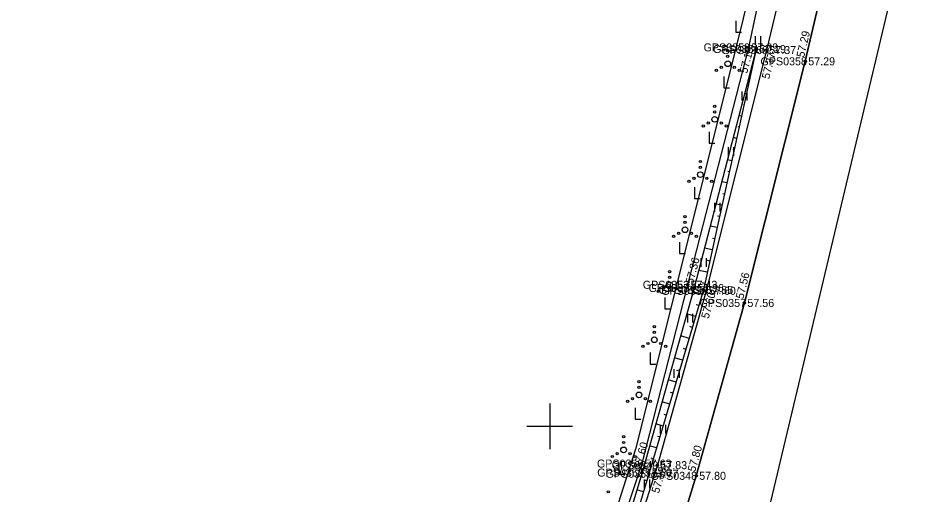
# Model space of a CAD drawing. Extents: x 551623 to 559850, y 6561220 to 6567135.
# Drawn here: x 556603.5 to 556683.3, y 6562994 to 6563035.7 of the extents above; entities that cross this region are included whole.
import ezdxf

# ---------------------------------------------------------------- set-up
doc = ezdxf.new("R2010")
doc.units = 0
for name, color, linetype in [('HALJASTUS', 7, 'Continuous'), ('KORGUS-EH2000', 7, 'Continuous'), ('MOOTKORG-EH2000', 7, 'Continuous'), ('MOOTMPUNKT', 7, 'Continuous'), ('MOOTNR', 7, 'Continuous'), ('MOOTPIIR', 7, 'Continuous'), ('PIIR', 7, 'Continuous'), ('RELJEEF', 7, 'Continuous'), ('TEE', 7, 'Continuous'), ('VORK', 7, 'Continuous')]:
    doc.layers.add(name, color=color, linetype=linetype)

msp = doc.modelspace()

# ---------------------------------------------------------------- linework, layer by layer
at = {"layer": 'HALJASTUS'}
for p, q in [((556666.281, 6563035.489), (556666.281, 6563034.489)), ((556666.281, 6563034.489), (556666.781, 6563034.489)), ((556667.98, 6563034.138), (556667.98, 6563033.377)), ((556668.435, 6563034.138), (556668.435, 6563033.377)), ((556665.226, 6563030.602), (556665.226, 6563029.602)), ((556665.226, 6563029.602), (556665.726, 6563029.602)), ((556666.792, 6563029.281), (556666.792, 6563028.52)), ((556667.247, 6563029.281), (556667.247, 6563028.52)), ((556663.952, 6563025.767), (556663.952, 6563024.767)), ((556663.952, 6563024.767), (556664.452, 6563024.767)), ((556665.605, 6563024.424), (556665.605, 6563023.663)), ((556666.06, 6563024.424), (556666.06, 6563023.663)), ((556662.657, 6563020.938), (556662.657, 6563019.938)), ((556662.657, 6563019.938), (556663.157, 6563019.938)), ((556664.418, 6563019.567), (556664.418, 6563018.806)), ((556664.873, 6563019.567), (556664.873, 6563018.806)), ((556661.363, 6563016.108), (556661.363, 6563015.108)), ((556661.363, 6563015.108), (556661.863, 6563015.108)), ((556663.231, 6563014.71), (556663.231, 6563013.949)), ((556663.686, 6563014.71), (556663.686, 6563013.949)), ((556660.068, 6563011.278), (556660.068, 6563010.278)), ((556660.068, 6563010.278), (556660.568, 6563010.278)), ((556662.044, 6563009.853), (556662.044, 6563009.092)), ((556662.499, 6563009.853), (556662.499, 6563009.092)), ((556658.774, 6563006.449), (556658.774, 6563005.449)), ((556658.774, 6563005.449), (556659.274, 6563005.449)), ((556660.856, 6563004.996), (556660.856, 6563004.235)), ((556661.311, 6563004.996), (556661.311, 6563004.235)), ((556657.479, 6563001.619), (556657.479, 6563000.619)), ((556657.479, 6563000.619), (556657.979, 6563000.619)), ((556659.669, 6563000.139), (556659.669, 6562999.378)), ((556660.124, 6563000.139), (556660.124, 6562999.378)), ((556656.057, 6562996.826), (556656.057, 6562995.826)), ((556656.057, 6562995.826), (556656.557, 6562995.826)), ((556658.263, 6562995.342), (556658.263, 6562994.58)), ((556658.718, 6562995.342), (556658.718, 6562994.58))]:
    msp.add_line(p, q, dxfattribs=at)
msp.add_lwpolyline([(556730.179, 6563321.969), (556724.636, 6563294.498), (556716.875, 6563261.024), (556713.058, 6563244.418), (556708.579, 6563223.732), (556703.725, 6563202.879), (556698.774, 6563180.185), (556694.069, 6563158.747), (556689.217, 6563135.017), (556684.659, 6563113.963), (556681.417, 6563095.607), (556676.704, 6563073.757), (556671.602, 6563053.044), (556667.381, 6563033.155), (556662.058, 6563012.385), (556658.05, 6562996.741), (556653.492, 6562982.863), (556651.045, 6562972.787), (556648.491, 6562966.927), (556641.785, 6562944.892), (556639.351, 6562934.359)], dxfattribs=at)
for centre, radius in [((556665.575, 6563032.875), 0.1), ((556665.575, 6563032.375), 0.1), ((556665.01, 6563031.4), 0.1), ((556665.575, 6563031.725), 0.25), ((556666.14, 6563031.4), 0.1), ((556664.575, 6563031.15), 0.1), ((556666.575, 6563031.15), 0.1), ((556664.435, 6563028.007), 0.1), ((556664.435, 6563027.507), 0.1), ((556663.87, 6563026.532), 0.1), ((556664.435, 6563026.857), 0.25), ((556665, 6563026.532), 0.1), ((556663.435, 6563026.282), 0.1), ((556665.435, 6563026.282), 0.1), ((556663.175, 6563023.169), 0.1), ((556663.175, 6563022.669), 0.1), ((556662.61, 6563021.694), 0.1), ((556663.175, 6563022.019), 0.25), ((556663.74, 6563021.694), 0.1), ((556662.175, 6563021.444), 0.1), ((556664.175, 6563021.444), 0.1), ((556661.833, 6563018.353), 0.1), ((556661.833, 6563017.853), 0.1), ((556661.833, 6563017.203), 0.25), ((556660.833, 6563016.628), 0.1), ((556661.268, 6563016.878), 0.1), ((556662.398, 6563016.878), 0.1), ((556662.833, 6563016.628), 0.1), ((556660.49, 6563013.536), 0.1), ((556660.49, 6563013.036), 0.1), ((556660.49, 6563012.386), 0.25), ((556659.49, 6563011.811), 0.1), ((556659.925, 6563012.061), 0.1), ((556661.055, 6563012.061), 0.1), ((556661.49, 6563011.811), 0.1), ((556659.148, 6563008.72), 0.1), ((556659.148, 6563008.22), 0.1), ((556659.148, 6563007.57), 0.25), ((556658.148, 6563006.995), 0.1), ((556658.583, 6563007.245), 0.1), ((556659.713, 6563007.245), 0.1), ((556660.148, 6563006.995), 0.1), ((556657.806, 6563003.903), 0.1), ((556657.806, 6563003.403), 0.1), ((556657.806, 6563002.753), 0.25), ((556656.806, 6563002.178), 0.1), ((556657.241, 6563002.428), 0.1), ((556658.371, 6563002.428), 0.1), ((556658.806, 6563002.178), 0.1), ((556656.463, 6562999.087), 0.1), ((556656.463, 6562998.587), 0.1), ((556656.463, 6562997.937), 0.25), ((556655.463, 6562997.362), 0.1), ((556655.898, 6562997.612), 0.1), ((556657.028, 6562997.612), 0.1), ((556657.463, 6562997.362), 0.1), ((556655.121, 6562994.27), 0.1)]:
    msp.add_circle(centre, radius, dxfattribs=at)
at = {"layer": 'KORGUS-EH2000'}
for centre in [(556668.063, 6563033.012), (556668.948, 6563032.918), (556672.356, 6563031.934), (556662.638, 6563012.103), (556663.677, 6563011.856), (556667.03, 6563010.794), (556659.413, 6562996.602), (556658.074, 6562995.952), (556662.813, 6562995.67)]:
    msp.add_circle(centre, 0.1, dxfattribs=at)
at = {"layer": 'MOOTMPUNKT'}
for centre in [(556667.381, 6563033.155), (556668.063, 6563033.012), (556668.948, 6563032.918), (556672.356, 6563031.934), (556662.058, 6563012.385), (556662.638, 6563012.103), (556663.448, 6563011.932), (556663.677, 6563011.856), (556667.03, 6563010.794), (556658.05, 6562996.741), (556659.413, 6562996.602), (556658.074, 6562995.952), (556658.666, 6562995.849), (556662.813, 6562995.67)]:
    msp.add_circle(centre, 0.1, dxfattribs=at)
at = {"layer": 'MOOTPIIR'}
for points in [[(556730.032, 6563322.014), (556724.172, 6563296.078), (556712.209, 6563244.927), (556703.118, 6563205.314), (556697.492, 6563180.798), (556687.922, 6563135.477), (556675.757, 6563074.837), (556666.859, 6563035.417), (556657.51, 6562997.998), (556646.614, 6562963.869), (556636.734, 6562934.522), (556635.188, 6562922.976), (556635.168, 6562919.001), (556632.094, 6562895.441), (556631.237, 6562879.275), (556626.788, 6562853.34), (556618.715, 6562822.195), (556606.273, 6562747.18)], [(556615.494, 6562765.342), (556618.725, 6562784.886), (556621.895, 6562802.833), (556624.976, 6562818.135), (556627.451, 6562830.139), (556630.417, 6562842.272), (556632.841, 6562852.218), (556634.314, 6562860.895), (556636.03, 6562872.421), (556636.878, 6562879.2), (556638.458, 6562894.387), (556639.853, 6562906.55), (556642.2, 6562921.204), (556644.444, 6562933.125), (556647.058, 6562944.293), (556652.609, 6562963.065), (556658.348, 6562981.124), (556662.813, 6562995.67), (556667.03, 6563010.794), (556672.356, 6563031.934), (556677.036, 6563051.97)]]:
    msp.add_lwpolyline(points, dxfattribs=at)
at = {"layer": 'PIIR'}
msp.add_lwpolyline([(555805.16, 6562850.3), (555826.95, 6563063.64), (555846.51, 6563164.12), (555894.51, 6563325.36), (556136, 6563572.22), (556237.49, 6563672.14), (556288.75, 6563676.33), (556560.07, 6563698.51), (556620.28, 6563801.97), (556702.51, 6563943.25), (556780.4, 6563955.1), (556879.9, 6563970.48), (556759.6, 6563438.6), (556685.3, 6563096.1), (556692.98, 6563093.02), (556667.97, 6562987.78), (556646.18, 6562894.39), (556231.34, 6562873.47), (556132.45, 6562866.66), (555973.8, 6562858.59)], close=True, dxfattribs=at)
at = {"layer": 'RELJEEF'}
for p, q in [((556667.635, 6563031.058), (556667.561, 6563031.075)), ((556667.422, 6563030.081), (556667.388, 6563030.089)), ((556667.208, 6563029.104), (556667.058, 6563029.137)), ((556666.994, 6563028.128), (556666.938, 6563028.14)), ((556666.78, 6563027.151), (556666.555, 6563027.2)), ((556666.566, 6563026.174), (556666.487, 6563026.191)), ((556666.352, 6563025.197), (556666.053, 6563025.263)), ((556666.138, 6563024.22), (556666.037, 6563024.242)), ((556665.924, 6563023.243), (556665.55, 6563023.325)), ((556665.71, 6563022.266), (556665.587, 6563022.294)), ((556665.496, 6563021.29), (556665.047, 6563021.388)), ((556665.283, 6563020.313), (556665.137, 6563020.345)), ((556665.069, 6563019.336), (556664.545, 6563019.451)), ((556664.855, 6563018.359), (556664.686, 6563018.396)), ((556664.641, 6563017.382), (556664.042, 6563017.513)), ((556664.427, 6563016.405), (556664.236, 6563016.447)), ((556664.213, 6563015.428), (556663.539, 6563015.576)), ((556663.999, 6563014.452), (556663.786, 6563014.498)), ((556663.785, 6563013.475), (556663.037, 6563013.639)), ((556663.571, 6563012.498), (556663.336, 6563012.55)), ((556663.328, 6563011.529), (556662.542, 6563011.762)), ((556663.043, 6563010.57), (556662.811, 6563010.639)), ((556662.758, 6563009.612), (556661.998, 6563009.838)), ((556662.473, 6563008.653), (556662.249, 6563008.72)), ((556662.188, 6563007.695), (556661.454, 6563007.913)), ((556661.903, 6563006.736), (556661.686, 6563006.8)), ((556661.618, 6563005.778), (556660.91, 6563005.988)), ((556661.333, 6563004.819), (556661.124, 6563004.881)), ((556661.048, 6563003.861), (556660.366, 6563004.063)), ((556660.763, 6563002.902), (556660.562, 6563002.962)), ((556660.478, 6563001.943), (556659.822, 6563002.138)), ((556660.193, 6563000.985), (556660, 6563001.042)), ((556659.908, 6563000.026), (556659.279, 6563000.213)), ((556659.623, 6562999.068), (556659.438, 6562999.123)), ((556659.338, 6562998.109), (556658.735, 6562998.289)), ((556659.053, 6562997.151), (556658.876, 6562997.203)), ((556658.768, 6562996.192), (556658.191, 6562996.364)), ((556658.482, 6562995.234), (556658.31, 6562995.285)), ((556658.196, 6562994.276), (556657.622, 6562994.447))]:
    msp.add_line(p, q, dxfattribs=at)
for points in [[(556668.063, 6563033.012), (556662.638, 6563012.103), (556658.074, 6562995.952), (556654.068, 6562982.624), (556648.67, 6562964.128), (556645.882, 6562956.383)], [(556668.063, 6563033.012), (556663.448, 6563011.932), (556658.666, 6562995.849), (556654.666, 6562982.46), (556649.054, 6562963.975), (556645.882, 6562956.383)]]:
    msp.add_lwpolyline(points, dxfattribs=at)
at = {"layer": 'TEE'}
for points in [[(556673.702, 6563052.755), (556668.948, 6563032.918), (556663.677, 6563011.856), (556659.413, 6562996.602), (556654.921, 6562982.331), (556649.346, 6562963.956), (556643.856, 6562944.887), (556641.251, 6562934.032), (556638.558, 6562921.526), (556636.805, 6562918.668), (556636.945, 6562916.523), (556637.3, 6562914.816), (556636.499, 6562907.225), (556635.077, 6562894.963), (556633.622, 6562879.411), (556632.944, 6562873.135), (556630.86, 6562861.302), (556629.252, 6562852.948), (556627.08, 6562842.719), (556624.546, 6562830.858), (556621.61, 6562818.841), (556618.964, 6562803.304), (556615.61, 6562785.44), (556612.253, 6562766.582)], [(556677.036, 6563051.97), (556672.356, 6563031.934), (556667.03, 6563010.794), (556662.813, 6562995.67), (556658.348, 6562981.124), (556652.609, 6562963.065), (556647.058, 6562944.293), (556644.444, 6562933.125), (556642.2, 6562921.204), (556639.853, 6562906.55), (556638.458, 6562894.387), (556636.878, 6562879.2), (556636.03, 6562872.421), (556634.314, 6562860.895), (556632.841, 6562852.218), (556630.417, 6562842.272), (556627.451, 6562830.139), (556624.976, 6562818.135), (556621.895, 6562802.833), (556618.725, 6562784.886), (556615.494, 6562765.342)]]:
    msp.add_lwpolyline(points, dxfattribs=at)
at = {"layer": 'VORK'}
for p, q in [((556650, 6563002), (556650, 6562998)), ((556648, 6563000), (556652, 6563000))]:
    msp.add_line(p, q, dxfattribs=at)

# ---------------------------------------------------------------- texts
at = {"layer": 'KORGUS-EH2000'}
for s, rotation, p in [(' 57.29', 76.85448, (556672.186, 6563031.974)), (' 57.19', 75.45465, (556667.198, 6563030.574)), (' 57.37', 75.95044, (556669.141, 6563030.09)), (' 57.36', 75.45465, (556662.469, 6563012.146)), (' 57.56', 75.85903, (556666.861, 6563010.837)), (' 57.60', 74.38264, (556663.825, 6563009.118)), (' 57.60', 74.2216, (556657.906, 6562996)), (' 57.80', 74.41953, (556662.645, 6562995.717)), (' 57.83', 72.52713, (556659.461, 6562993.836))]:
    msp.add_text(s, height=0.7, rotation=rotation, dxfattribs=at).set_placement(p)
at = {"layer": 'MOOTKORG-EH2000'}
for s, p in [(' 57.09', (556667.381, 6563032.805)), (' 57.19', (556668.063, 6563032.662)), (' 57.37', (556668.948, 6563032.568)), (' 57.29', (556672.356, 6563031.584)), (' 57.43', (556662.058, 6563012.035)), (' 57.36', (556662.638, 6563011.753)), (' 57.55', (556663.448, 6563011.582)), (' 57.60', (556663.677, 6563011.506)), (' 57.56', (556667.03, 6563010.444)), (' 57.63', (556658.05, 6562996.391)), (' 57.60', (556658.074, 6562995.602)), (' 57.83', (556659.413, 6562996.252)), (' 57.77', (556658.666, 6562995.499)), (' 57.80', (556662.813, 6562995.32))]:
    msp.add_text(s, height=0.7, dxfattribs=at).set_placement(p)
at = {"layer": 'MOOTNR'}
for s, p in [('GPS0359 ', (556663.461, 6563032.805)), ('GPS0361 ', (556664.283, 6563032.662)), ('GPS0360 ', (556665.028, 6563032.568)), ('GPS0358 ', (556668.437, 6563031.584)), ('GPS0353 ', (556658.138, 6563012.035)), ('GPS0354 ', (556658.648, 6563011.753)), ('GPS0355 ', (556659.528, 6563011.582)), ('GPS0356 ', (556659.758, 6563011.506)), ('GPS0357 ', (556663.111, 6563010.444)), ('GPS0350 ', (556654.131, 6562996.391)), ('GPS0352 ', (556654.155, 6562995.602)), ('GPS0349 ', (556655.423, 6562996.252)), ('GPS0351 ', (556654.886, 6562995.499)), ('GPS0348 ', (556658.824, 6562995.32))]:
    msp.add_text(s, height=0.7, dxfattribs=at).set_placement(p)

doc.saveas('drawing.dxf')
